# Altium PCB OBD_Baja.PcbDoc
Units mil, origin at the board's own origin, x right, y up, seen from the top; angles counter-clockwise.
Board outline 2500 x 3250 mil, 2 copper layers (Top Layer, Bottom Layer); 34 components, 27 nets, 137 pads, 53 vias.
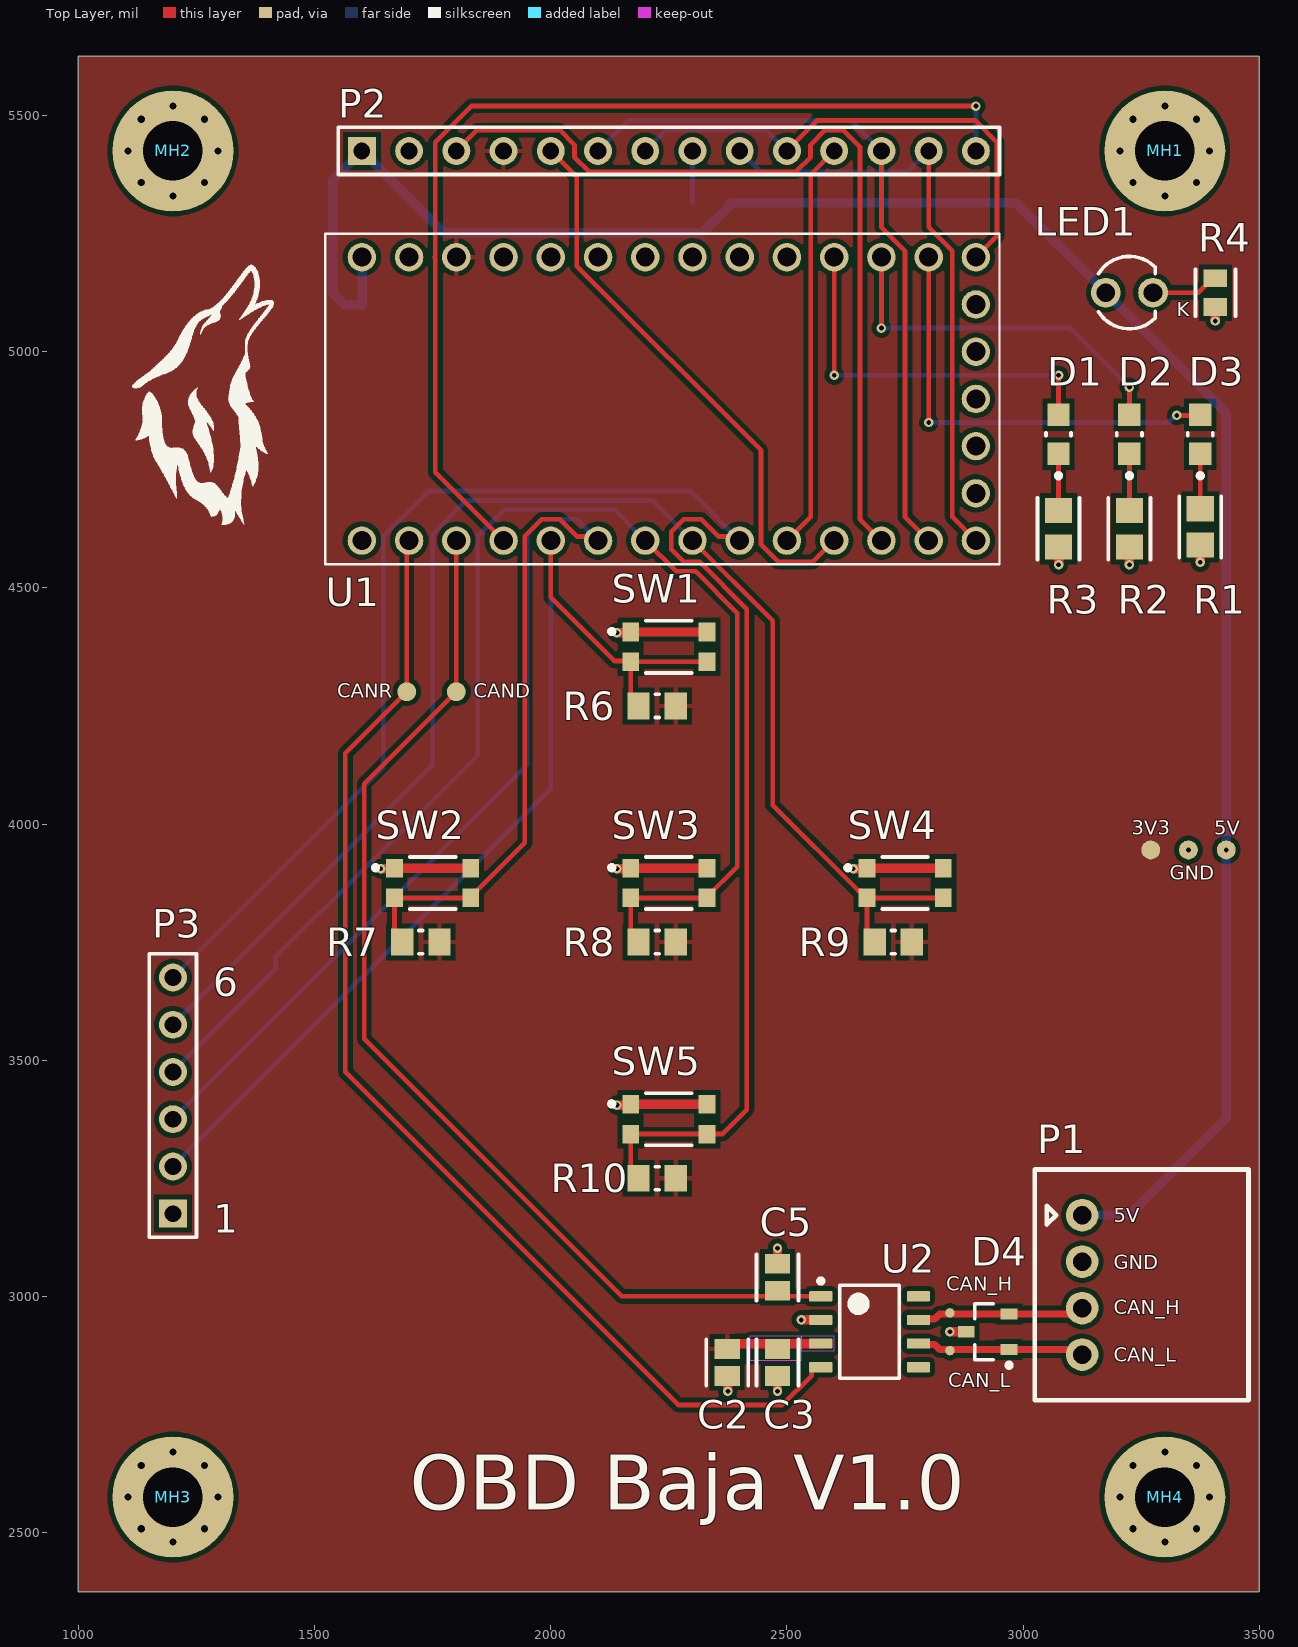
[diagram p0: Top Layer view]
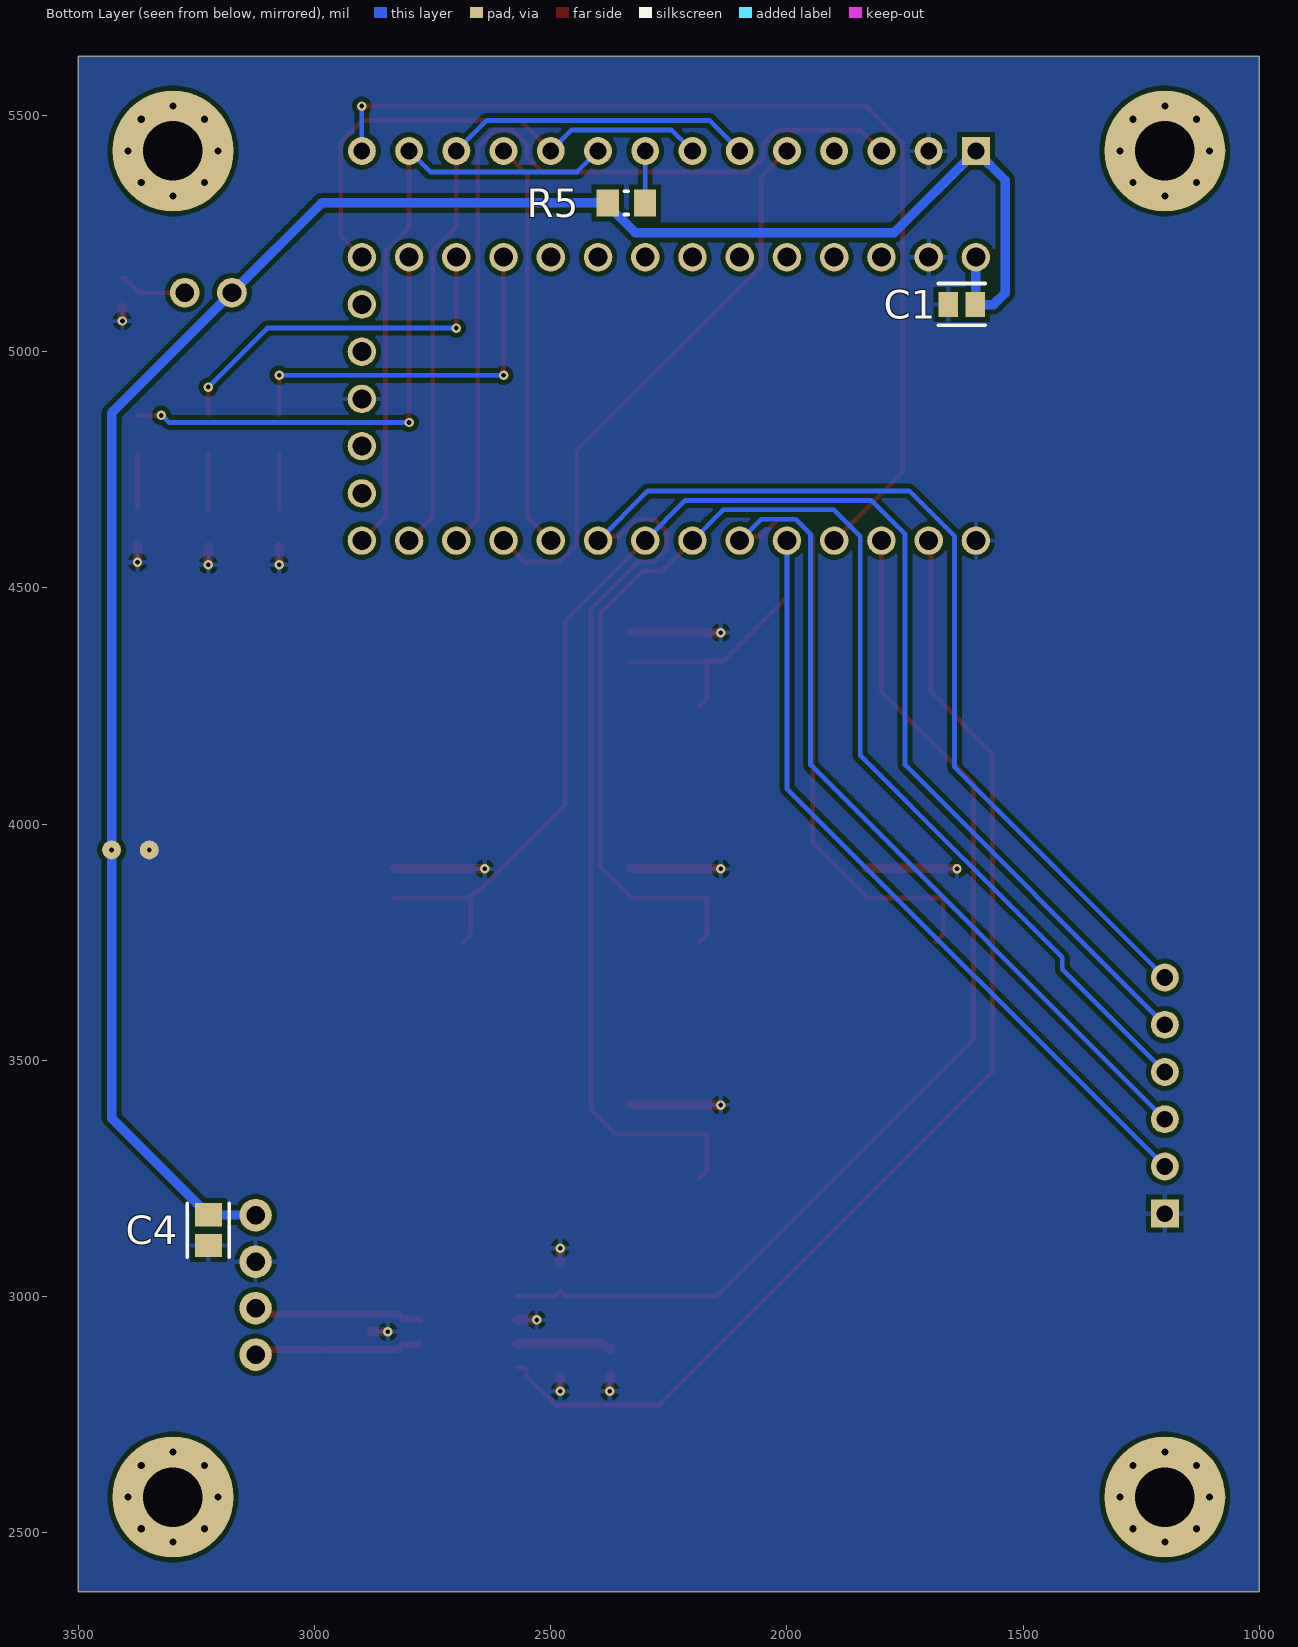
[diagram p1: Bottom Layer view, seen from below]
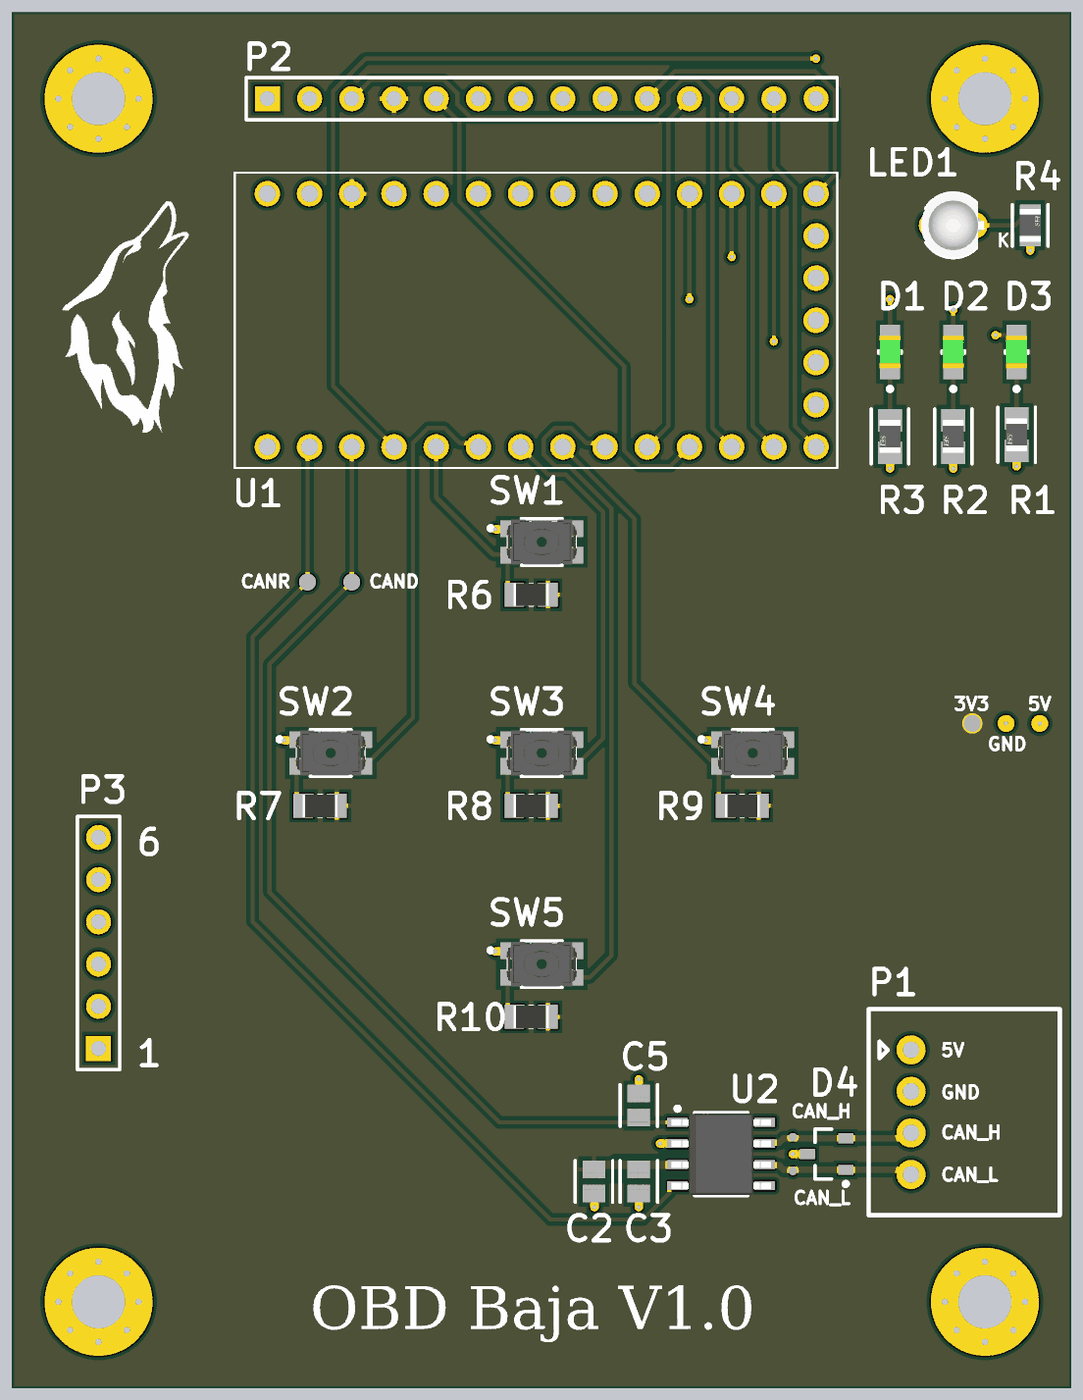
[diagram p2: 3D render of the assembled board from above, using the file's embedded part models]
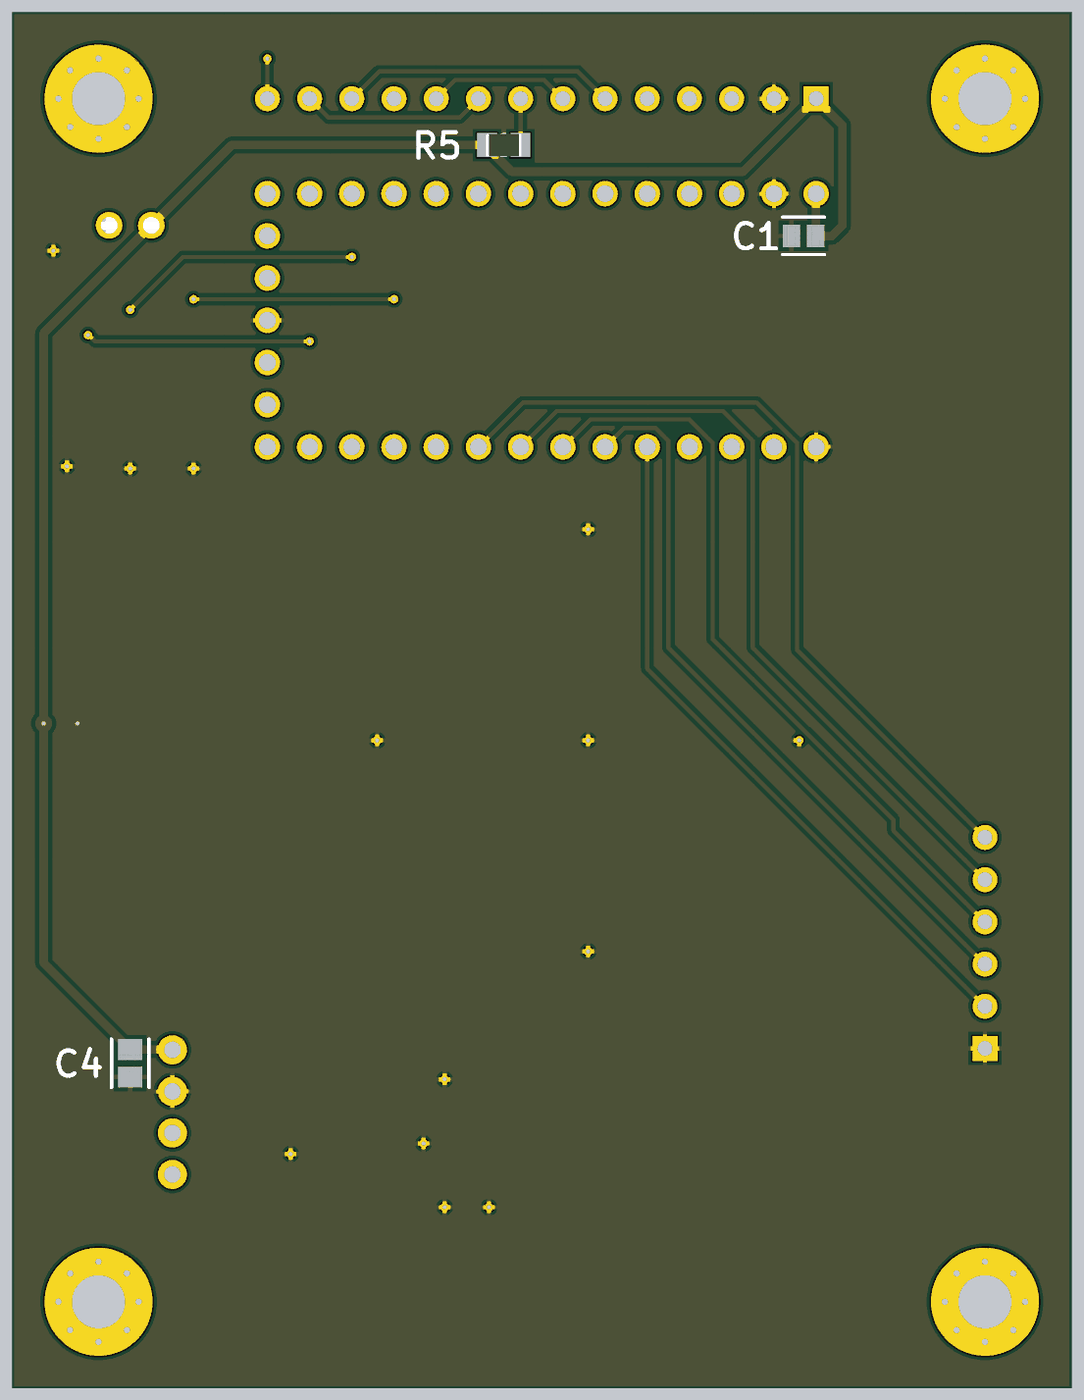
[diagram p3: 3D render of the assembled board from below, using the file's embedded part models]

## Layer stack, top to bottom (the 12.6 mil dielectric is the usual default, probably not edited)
Top Solder: solder mask 0.4, Solder Resist, Dk 3.5
Top Layer: signal copper 1.4
Dielectric 1: dielectric 12.6, FR-4, Dk 4.8
Bottom Layer: signal copper 1.4
Bottom Solder: solder mask 0.4, Solder Resist, Dk 3.5

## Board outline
1000,2375 1000,5625 3500,5625 3500,2375

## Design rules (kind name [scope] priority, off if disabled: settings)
Clearance [All] p1: gap=10 ignorepadtopadclearanceinfootprint=FALSE except(0: Arc-Hole Track-Hole SMDPad-Hole THPad-Hole Via-Hole Fill-Hole Poly-Hole Region-Hole Text-Hole)
DiffPairsRouting [All] p1: maxlimit=10 minlimit=10 mostfreqgap=10 toplayer_minwidth=15 toplayer_maxwidth=15 toplayer_prefwidth=15 bottomlayer_minwidth=15 bottomlayer_maxwidth=15 bottomlayer_prefwidth=15 maxuncoupledlength=500
HoleSize [All] p1: absolutevalues=TRUE maxlimit=200 minlimit=1 maxpercent=80.000 minpercent=20.000
NetAntennae [All] p1 off: netantennaetolerance=0
PolygonConnect [All] p1: connectstyle=Relief reliefconductorwidth=10 reliefentries=4 polygonreliefangle="90 Angle" airgapwidth=10
RoomDefinition Transceiver [InComponentClass('Transceiver')] p1 off: confinementstyle=ConfineIn formatcopy=TRUE lockcomponents=FALSE outline 0,0 2000,0 2000,1000 0,1000
RoomDefinition Screen [InComponentClass('Screen')] p2 off: confinementstyle=ConfineIn formatcopy=TRUE lockcomponents=FALSE outline 0,0 2000,0 2000,1000 0,1000
RoomDefinition LEDs [InComponentClass('LEDs')] p3 off: confinementstyle=ConfineIn formatcopy=TRUE lockcomponents=FALSE outline 0,0 2000,0 2000,1000 0,1000
RoomDefinition Buttons [InComponentClass('Buttons')] p4 off: confinementstyle=ConfineIn formatcopy=TRUE lockcomponents=FALSE outline 0,0 2000,0 2000,1000 0,1000
RoomDefinition OBD_Baja [InComponentClass('OBD_Baja')] p5: confinementstyle=ConfineIn formatcopy=TRUE lockcomponents=FALSE outline 1000,2375 3500,2375 3500,5625 1000,5625
RoutingVias [All] p1: holewidth=10 width=20 viastyle="Through Hole" minholewidth=10 minwidth=20 maxholewidth=10 maxwidth=20
SilkToSolderMaskClearance [IsPad] p1: minsilkscreentomaskgap=5 clearancetoexposedcopper=TRUE
SolderMaskExpansion [All] p1: expansion=4 istentingtop=FALSE
Width Power_Width [InNetClass('Power')] p1: maxlimit=20 minlimit=20 preferedwidth=20 minimp=50.000000 maximp=50.000000 favimp=50.000000
Width [All] p2: maxlimit=10 minlimit=10 preferedwidth=10
26 further rules are at their usual default settings.

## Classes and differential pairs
component class Transceiver: C2 C3 C4 C5 D4 P1 U2
component class OBD_Baja: C1 MH1 MH2 MH3 MH4 U1
component class Screen: P2 R5
component class LEDs: D1 D2 D3 LED1 R1 R2 R3 R4
net class Power: 3V3 +5 GND
component class Buttons: P3 R6 R7 R8 R9 R10 SW1 SW2 SW3 SW4 SW5
differential pair CAN: +CAN_H -CAN_L

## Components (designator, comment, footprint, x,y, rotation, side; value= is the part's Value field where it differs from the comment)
C1 "CL21B104KACNNNC" FP-CL21-IPC_C 1630,5100 r0 bottom
C2 "CL21B104KACNNNC" FP-CL21-IPC_C 2373.53,2860 r90 top
C3 "CL21B104KACNNNC" FP-CL21-IPC_C 2480,2860 r90 top
C4 "CL21A106KOQNNNE" FP-CL21-IPC_B 3225,3140 r270 bottom
C5 "CL21B103KAANNNC" FP-CL21-IPC_C 2480,3040 r90 top
D1 "LTST-C170GKT" FP-LTST-C170GKT-MFG 3075,4825 r90 top
D2 "LTST-C170GKT" FP-LTST-C170GKT-MFG 3225,4825 r90 top
D3 "LTST-C170GKT" FP-LTST-C170GKT-MFG 3375,4825 r90 top
D4 "PESD3V3L2BT,215" SOT95P230X110-3N 2925,2925 r180 top
LED1 "151031SS04000" "Type 3mm" 3225,5125 r0 top
MH1 "Mounting_Hole_M3" Mounting_Hole_M3 3300,5425 r0 top
MH2 "Mounting_Hole_M3" Mounting_Hole_M3 1200,5425 r0 top
MH3 "Mounting_Hole_M3" Mounting_Hole_M3 1200,2575 r0 top locked
MH4 "Mounting_Hole_M3" Mounting_Hole_M3 3300,2575 r0 top
P1 "0534" 0534260410 3125,3171.85 r270 top locked
P2 "Header 14" HDR1X14 1600,5425 r0 top locked
P3 "Header 6" HDR1X6 1200,3175 r90 top
R1 "RMCF0805JT240R" FP-RMCF0805-IPC_A 3375,4628.84 r270 top
R2 "RMCF0805JT240R" FP-RMCF0805-IPC_A 3225,4625 r270 top
R3 "RMCF0805JT240R" FP-RMCF0805-IPC_A 3075,4625 r270 top
R4 "RMCF0805JT680R" FP-RMCF0805-IPC_C 3407.26,5125 r90 top
R5 "RC0805FR-07100RL" RESC2013X60X35ML10T20 2340,5315 r180 bottom
R6 "RC0805JR-0710KL" RESC2013X60X35ML10T20 2225,4250 r0 top
R7 "RC0805JR-0710KL" RESC2013X60X35ML10T20 1725,3750 r0 top
R8 "RC0805JR-0710KL" RESC2013X60X35ML10T20 2225,3750 r0 top
R9 "RC0805JR-0710KL" RESC2013X60X35ML10T20 2725,3750 r0 top
R10 "RC0805JR-0710KL" RESC2013X60X35ML10T20 2225,3250 r0 top
SW1 "KMR631NG ULC LFS" FP-KMR631NG_ULC_LFS-MFG 2250,4375 r0 top
SW2 "KMR631NG ULC LFS" FP-KMR631NG_ULC_LFS-MFG 1750,3875 r0 top
SW3 "KMR631NG ULC LFS" FP-KMR631NG_ULC_LFS-MFG 2250,3875 r0 top
SW4 "KMR631NG ULC LFS" FP-KMR631NG_ULC_LFS-MFG 2750,3875 r0 top
SW5 "KMR631NG ULC LFS" FP-KMR631NG_ULC_LFS-MFG 2250,3375 r0 top
U1 "DEV-15583" MODULE_DEV-15583 2250,4900 r90 top
U2 "SN65HVD232D" D0008A_L 2675,2925 r0 top

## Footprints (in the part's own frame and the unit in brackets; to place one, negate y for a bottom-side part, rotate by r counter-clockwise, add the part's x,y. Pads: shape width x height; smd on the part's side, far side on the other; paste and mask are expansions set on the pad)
0534260410 [mm] "Molex 0534260410, Connector Header Through Hole, Right Angle 4 position 0.098\" (2.50mm)"
  round 1.75 hole 1: 1(0,0) 2(2.5,0) 3(5,0) 4(7.5,0)
  silkscreen extent -2.45,-2.55 9.95,8.95
D0008A_L [mm] "SOIC, 8-Leads, Body 5x4mm, Pitch 1.27mm, IPC High Density"
  rrect18% 1.25x0.55 smd: 1(-2.625,1.905) 2(-2.625,0.635) 3(-2.625,-0.635) 4(-2.625,-1.905) 5(2.625,-1.905) 6(2.625,-0.635) 7(2.625,0.635) 8(2.625,1.905)
  silkscreen extent -2.75,-2.5 1.6,2.85, body extent -3,-2.45 3,2.45, height 1.63
FP-CL21-IPC_B [mil]
  rect 49.4x57.33 smd paste+0 mask+0: 1(-32.51,0) 2(32.51,0)
  silkscreen extent -57,-44 57,44, body extent -39,-25 39,25, height 57
FP-CL21-IPC_C [mil]
  rect 41.52x53.39 smd paste+0 mask+0: 1(-28.57,0) 2(28.57,0)
  silkscreen extent -49,-44 49,44, body extent -39,-25 39,25, height 57
FP-KMR631NG_ULC_LFS-MFG [mm]
  rect 0.9x1 smd paste+0 mask+0: 1(-2.05,0.8) 2(2.05,0.8) 3(-2.05,-0.8) 4(2.05,-0.8)
  silkscreen extent -3.2,-1.4 1.22,1.4, body extent -2.6,-1.5 2.6,1.5, height 0.25
FP-LTST-C170GKT-MFG [mm]
  rect 1.2x1.2 smd paste+0 mask+0: 1(-1.05,0) 2(1.05,0)
  silkscreen extent -2.35,-0.67 0.08,0.67, body extent -1.75,-0.77 1.75,0.77, height 0.25
FP-RMCF0805-IPC_A [mil]
  rect 53.33x57.56 smd paste+0 mask+0: 1(-38.42,0) 2(38.42,0)
  silkscreen extent -65,-45 65,45, body extent -85,-48 85,48, height 10
FP-RMCF0805-IPC_C [mil]
  rect 37.58x49.69 smd paste+0 mask+0: 1(-30.54,0) 2(30.54,0)
  silkscreen extent -49,-42 49,42, body extent -53,-31 53,31, height 10
HDR1X6 [mm] "Connector; Header; 6 Position"
  rect 1.5x1.5 hole 0.9: 1(0,0)
  round 1.5 hole 0.9: 2(2.54,0) 3(5.08,0) 4(7.62,0) 5(10.16,0) 6(12.7,0)
  silkscreen extent -1.27,-1.27 13.97,1.27
HDR1X14 [mm] "Connector; Header; 14 Position"
  rect 1.5x1.5 hole 0.9: 1(0,0)
  round 1.5 hole 0.9: 2(2.54,0) 3(5.08,0) 4(7.62,0) 5(10.16,0) 6(12.7,0) 7(15.24,0) 8(17.78,0) 9(20.32,0) 10(22.86,0) 11(25.4,0) 12(27.94,0) 13(30.48,0) 14(33.02,0)
  silkscreen extent -1.27,-1.27 34.29,1.27
MODULE_DEV-15583 [mm]
  round 1.53 hole 1.02: 0(-7.62,13.97) 1(-7.62,11.43) 2(-7.62,8.89) 3(-7.62,6.35) 3.3V_1(-2.54,-16.51) 3.3V_2(7.62,11.43) 4(-7.62,3.81) 5(-7.62,1.27) 6(-7.62,-1.27) 7(-7.62,-3.81) 8(-7.62,-6.35) 9(-7.62,-8.89) 10(-7.62,-11.43) 11(-7.62,-13.97) 12(-7.62,-16.51) 13(7.62,-16.51) 14(7.62,-13.97) 15(7.62,-11.43) 16(7.62,-8.89) 17(7.62,-6.35) 18(7.62,-3.81) 19(7.62,-1.27) 20(7.62,1.27) 21(7.62,3.81) 22(7.62,6.35) 23(7.62,8.89) G1(-7.62,16.51) G2(0,-16.51) G3(7.62,13.97) ON-OFF(5.08,-16.51) PGM(2.54,-16.51) VBAT(-5.08,-16.51) VIN(7.62,16.51)
  silkscreen extent -8.89,-17.78 8.89,18.48
Mounting_Hole_M3 [mm] "Generic M3 Mounting Hole"
  round 6.5 hole 3.2: 1(0,0)
RESC2013X60X35ML10T20 [mm] "Chip Resistor, 2-Leads, Body 2.1x1.35mm, IPC Low Density"
  rect 1.2x1.45 smd: 1(-1,0) 2(1,0)
  silkscreen extent -0.1,-0.63 0.1,0.63, body extent -1.05,-0.68 1.05,0.67, height 0.6
SOT95P230X110-3N [mm] "SOT23, 3-Leads, Body 2.90x2.30mm, Pitch 0.95mm, IPC Medium Density"
  rect 0.9x0.6 smd: 1(-1.15,0.95) 2(-1.15,-0.95) 3(1.15,0)
  silkscreen extent -1.28,-1.5 0.7,1.92, body extent -0.7,-1.5 0.7,1.5, height 1.1
"Type 3mm" [mm] "THT, LED-3mm, 2pin- Body 4.15mm(max)"
  round 1.6 hole 1: 1(1.27,0) 2(-1.27,0)
  silkscreen extent -1.66,-1.95 1.4,1.95, body extent -1.93,-1.94 1.87,1.94, height 10.5

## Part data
C1 C2 C3: library part CMP-13271-002854-1, "CL21 Series 0805 100nF 25V ±10% Tolerance X7R Multilayer Ceramic Chip Capacitor", Capacitance=100nF, Case Code (Imperial)=0805, Case Code (Metric)=2012, Dielectric=X7R, Max Operating Temperature=125°C, Min Operating Temperature=-55°C, Package Quantity=1, Tolerance=10%, Voltage=25V
C4: library part CMP-2000-06102-2, "CL21 Series 0805 10uF 16V ±10% Tolerance X5R Multilayer Ceramic Chip Capacitor", Capacitance=10uF, Case Code (Imperial)=0805, Case Code (Metric)=2012, Dielectric=X7R, Max Operating Temperature=85°C, Min Operating Temperature=-55°C, Package Quantity=1, Tolerance=10%, Voltage=16V
C5: library part CMP-13271-004188-1, "CL21 Series 0805 10nF 25V ±10% Tolerance X7R Multilayer Ceramic Chip Capacitor", Capacitance=10nF, Case Code (Imperial)=0805, Case Code (Metric)=2012, Dielectric=X7R, Max Operating Temperature=125°C, Min Operating Temperature=-55°C, Package Quantity=1, Tolerance=20%, Voltage Rating=50V
D1 D2 D3: library part CMP-1674-00002-6, "LED GREEN CLEAR SMD", Case Code (Imperial)=0805, Case Code (Metric)=2012, Color=Green, Forward Current=30mA, Forward Voltage=2.1V, Lens Color=Colorless, Max Operating Temperature=85°C, Min Operating Temperature=-55°C, Package Quantity=1, Power Dissipation=100mW, Reverse Voltage=5V, Test Current=10mA
D4: library part CMP-00002-6, "PESD3V3L2BT - Low capacitance double bidirectional ESD protection diode in SOT23"
LED1: library part CMP-1488-00005-1, "THT LED round mono-color color lens, WL-TMRW, Super Red", Emitting color="Super Red", Manufacturer="Wuerth Elektronik"
MH1 MH2 MH3 MH4: library part CMP-00001-4, "Generic M3 Mounting Hole"
P1: library part CMP-00000-3, "2.50mm Pitch Mini-Lock Wire-to-Board Header Right Angle Friction and Positive Lock 4 Circuits", Color=White, Contact Resistance=20mR, Max Operating Temperature=105°C, Min Operating Temperature=-40°C
P2: "Header, 14-Pin"
P3: "Header, 6-Pin"
R1 R2 R3: library part CMP-26527-005851-1, "240Ω ±5% 0.125W 0805 Thick Film Chip Resistor AEC-Q200 compliant", Case Code (Imperial)=0805, Case Code (Metric)=2012, Max Operating Temperature=155°C, Max Power Dissipation=125mW, Min Operating Temperature=-55°C, Resistance=240R, Resistor Type="Thick Film", Temperature Coefficient=200ppm/°C, Tolerance=5%
R4: library part CMP-26527-000032-1, "680Ω ±5% 0.125W 0805 Thick Film Chip Resistor AEC-Q200 compliant", Case Code (Imperial)=0805, Case Code (Metric)=2012, Max Operating Temperature=155°C, Max Power Dissipation=125mW, Min Operating Temperature=-55°C, Resistance=680R, Resistor Type="Thick Film", Temperature Coefficient=200ppm/°C, Tolerance=5%
R5: library part CMP-2100-03669-1, "Chip Resistor, 100 Ohm, +/-1%, 0.125 W, -55 to 155 degC, 0805 (2012 Metric), RoHS, Tape and Reel", Case Code (Imperial)=0805, Case Code (Metric)=2012, Manufacturer=Yageo, Max Operating Temperature=155degC, Max Power Dissipation=125mW, Min Operating Temperature=-55degC, Package Description="2-Pin Surface Mounted Device, Body 2 x 1.25 mm", Package Quantity=1, Resistance=100Ohm, Temperature Coefficient=100ppm/degreesC, Tolerance=1%, Voltage Rating=150V
R6 R7 R8 R9 R10: library part CMP-2000-05025-1, "Chip Resistor, 10 KOhm, +/- 5%, 0.125 W, -55 to 155 degC, 0805 (2012 Metric), RoHS, Tape and Reel", Manufacturer=Yageo, Package Description="2-Pin Surface Mounted Device, Body 2 x 1.25 mm", Package Reference=805, Power Rating=250mW, Resistance=10kohm, Resistance Tolerance=±5%, Resistor Case Style=0805[2012Metric], Resistor Element Type=ThickFilm, Temperature Coefficient=±100ppm/degC, Voltage Rating=150V
SW1 SW2 SW3 SW4 SW5: library part CMP-10040-000019-1, "SWITCH TACTILE SPST-NO 50MA 32V", Max Operating Temperature=85°C, Min Operating Temperature=-40°C, Operating Force=300gf, Ratings=IP67
U1: library part CMP-301-000000-1, "RT1062 Teensy 4.0 i.MX ARMÂ® CortexÂ®-M7 MPU Embedded Evaluation Board", Package=None
U2: library part CMP-0315-00073-2, "3.3 V CAN Transceiver, 17 mA, -40 to 85 degC, 8-pin SOIC (D), Green (RoHS & no Sb/Br)", Drivers Per Package=1, Manufacturer="Texas Instruments", Rating=Catalog, Supply Voltage(s)(V)=3.3

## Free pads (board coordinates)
  round 40 hole 10 mask+4: 8(3430,3945) TP(3350,3945)
  round 40 smd: TP(1695,4280) TP(1800,4280) TP(3270,3945)
  round 20 smd: TP(2845,2885) TP(2845,2965)

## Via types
v1: diameter 25, hole 15, Top Layer to Bottom Layer, 32 vias
v2: diameter 20, hole 10, Top Layer to Bottom Layer, 21 vias

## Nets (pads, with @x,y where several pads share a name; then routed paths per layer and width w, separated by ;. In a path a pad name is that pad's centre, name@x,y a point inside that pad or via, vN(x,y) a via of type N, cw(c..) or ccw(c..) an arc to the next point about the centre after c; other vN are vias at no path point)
3V3: C2.2 C3.2 P2.4 pad.TP@3270,3945 R6.2 R7.2 R8.2 R9.2 R10.2 U1.3.3V_2 U2.3 | length 202.9
  Top Layer w20: C2.2 2379.47,2888.57 2390.89,2900 U2.3
+5: C1.1 C4.1 LED1.2 P1.1 P2.1 pad.8 R5.1 U1.VIN | length 4498.2
  Bottom Layer w20: U1.VIN 1600.71,5199.29 1600.71,5099.95 1601.04,5099.62 1562.38,5099.62 1538,5124 1538,5363 P2.1 1772.92,5252.08 2321.37,5252.08 2379.37,5310.08 R5.1 2985,5315 LED1.2 3430,4870 3430,3377.51 C4.1 3224.67,3172.18 3125.33,3172.18 P1.1
B_C: P3.4 R8.1 SW3.3 SW3.4 U1.5 | length 2956.4
  Top Layer w10: R8.1 2169.29,3766.34 SW3.3 SW3.4 2330.71,3845.47 2395,3909.76 2395,4446.6 2306.72,4534.88 2265.12,4534.88 U1.5
  Bottom Layer w10: P3.4 1417.02,3692.02 1417.02,3717.37 1624.82,3925.18 1625.18,3925.18 1845.12,4145.12 1845.12,4608.92 1901.31,4665.12 2134.88,4665.12 U1.5
B_DN: P3.6 R10.1 SW5.3 SW5.4 U1.7 | length 3808.3
  Top Layer w10: R10.1 2169.29,3266.34 SW5.3 SW5.4 2363.42,3343.5 2415,3395.08 2415,4454.88 2315,4554.88 2281.31,4554.88 2254.88,4581.31 2254.88,4618.69 2281.31,4645.12 2318.69,4645.12 2354.88,4608.92 2391.08,4608.92 U1.7
  Bottom Layer w10: P3.6 1645.12,4120.12 1645.12,4608.92 1741.31,4705.12 2294.88,4705.12 U1.7
B_L: P3.3 R7.1 SW2.3 SW2.4 U1.4 | length 2994.2
  Top Layer w10: R7.1 1669.29,3766.34 SW2.3 SW2.4 1830.71,3845.47 1945.12,3959.88 1945.12,4608.92 1981.31,4645.12 2018.69,4645.12 2054.88,4608.92 2091.08,4608.92 U1.4
  Bottom Layer w10: P3.3 1950,4125 1950,4613.81 1981.31,4645.12 2054.88,4645.12 U1.4
B_R: P3.5 R9.1 SW4.3 SW4.4 U1.6 | length 3055.6
  Top Layer w10: U1.6 2469.63,4430.37 2469.63,4040.02 2651.46,3858.19 2656.58,3858.19 2669.29,3845.47 SW4.3 ; R9.1 2669.29,3766.34 SW4.3 ; SW4.4 SW4.3
  Bottom Layer w10: P3.5 1750,4125 1750,4613.81 1821.31,4685.12 2214.88,4685.12 U1.6
B_UP: P3.2 R6.1 SW1.3 SW1.4 U1.3 | length 2263.9
  Top Layer w10: U1.3 2000,4480 2135,4345 2167.8,4345 SW1.3 ; R6.1 2169.29,4266.34 SW1.3 ; SW1.4 SW1.3
  Bottom Layer w10: P3.2 2000,4075 U1.3
CAN_H: D4.2 P1.3 pad.TP@2845,2965 U2.7 | length 351.1
  Top Layer w15: U2.7 2780.02,2951.67 2812.78,2951.67 2823.51,2962.4 D4.2 ; D4.2@2976.18,2962.4 3097.82,2962.4 3110.42,2975 P1.3
CAN_L: D4.1 P1.4 pad.TP@2845,2885 U2.6 | length 350.5
  Top Layer w15: U2.6 2780.02,2898.33 2812.78,2898.33 2823.51,2887.6 D4.1 ; D4.1@2976.18,2887.6 3099.39,2887.6 3110.42,2876.58 P1.4
CAND: C5.1 pad.TP@1800,4280 U1.1 U2.1 | length 2337.6
  Top Layer w10: U1.1 1800,4280 1605,4085 1605,3545 2150,3000 2468.57,3000 C5.1 2491.43,3000 U2.1
CANR: pad.TP@1695,4280 U1.0 U2.4 | length 2519.8
  Top Layer w10: U1.0 1695,4595 1695,4280 1565,4150 1565,3475 2270,2770 2490,2770 2552.05,2832.05 2552.05,2844.17 2557.87,2850 U2.4
CS: P2.3 U1.10 | length 1844.4
  Top Layer w10: P2.3 1844.53,5469.53 2018.44,5469.53 2050,5437.97 2050,5412.03 2081.56,5380.47 2518.44,5380.47 2550,5412.03 2550,5437.97 2581.56,5469.53 2618.44,5469.53 2654.42,5433.56 2654.42,4645.58 U1.10
D/C: P2.5 U1.9 | length 1206.9
  Top Layer w10: P2.5 2054.88,5370.12 2054.88,5181.31 2445.12,4791.08 2445.12,4591.08 2481.31,4554.88 2554.88,4554.88 U1.9
DEBUG1: D1.2 U1.16 | length 808.7
  Top Layer w10: v2(2600,4950) U1.16 ; D1.2 v2(3075,4950)
  Bottom Layer w10: v2(2600,4950) v2(3075,4950)
DEBUG2: D2.2 U1.15 | length 785.4
  Top Layer w10: v2(2700,5050) U1.15 ; D2.2 v2(3225,4925)
  Bottom Layer w10: v2(2700,5050) 3100,5050 v2(3225,4925)
DEBUG3: D3.2 U1.14 | length 931.8
  Top Layer w10: v2(2800,4850) U1.14 ; v2(3325,4865) 3373.66,4865 D3.2
  Bottom Layer w10: v2(2800,4850) 3307.29,4850 3322.29,4865 v2(3325,4865)
GND: C1.2 C2.1 C3.1 C4.2 C5.2 D4.3 P1.2 P2.2 P3.1 pad.TP@3350,3945 R1.2 R2.2 R3.2 R4.1 SW1.1 SW1.2 SW2.1 SW2.2 SW3.1 SW3.2 SW4.1 SW4.2 SW5.1 SW5.2 U1.G1 U1.G2 U1.G3 U2.2 | length 1273.1
  Top Layer w20: v2(1640,3905) 1667.8,3905 SW2.1 SW2.2 ; v2(2140,3405) 2167.8,3405 SW5.1 SW5.2 ; v2(2140,3905) 2167.8,3905 SW3.1 SW3.2 ; v2(2140,4405) 2166.58,4405 2168.07,4406.5 SW1.2 ; C2.1 2375,2829.96 v2(2375,2799) ; v2(2480,2799) C3.1 ; C5.2 v2(2480,3102) ; v2(2530,2950) U2.2 ; v2(2640,3905) 2667.8,3905 SW4.1 SW4.2 ; v2(2845,2925) D4.3 ; v2(3075,4549) R3.2 ; v2(3225,4549) R2.2 ; v2(3375,4554) R1.2 ; v2(3407,5065) 3407,5094.19 R4.1
NetD1_1: D1.1 R3.1 | length 120.2
  Top Layer w10: R3.1 D1.1
NetD2_1: D2.1 R2.1 | length 120.2
  Top Layer w10: R2.1 D2.1
NetD3_1: D3.1 R1.1 | length 116.4
  Top Layer w10: R1.1 D3.1
NetLED1_1: LED1.1 R4.2 | length 144.9
  Top Layer w10: LED1.1 3370.67,5125 3401.21,5155.54 R4.2
NetP2_8: P2.8 R5.2 | length 110.3
  Bottom Layer w10: P2.8 2300,5315.63 R5.2
SCK: P2.7 P2.10 U1.13 | length 1089.1
  Top Layer w10: P2.10 2564.53,5489.53 2898.44,5489.53 2944.53,5443.44 2944.53,5244.53 U1.13
  Bottom Layer w10: P2.7 2244.53,5469.53 2455.47,5469.53 P2.10
SDI: P2.6 P2.12 U1.11 | length 1519.9
  Top Layer w10: P2.12 2700,5263.81 2749.89,5213.92 2749.89,4650.11 U1.11
  Bottom Layer w10: P2.6 2164.53,5489.53 2635.47,5489.53 P2.12
SDO: P2.9 P2.13 U1.12 | length 1303.3
  Top Layer w10: P2.13 2800,5263.81 2849.89,5213.92 2849.89,4650.11 U1.12
  Bottom Layer w10: P2.9 2444.53,5380.47 2755.47,5380.47 P2.13
T_CS: P2.11 U1.8 | length 866.4
  Top Layer w10: U1.8 2550.11,4650.11 2550.11,5375.11 P2.11
T_IRQ: P2.14 U1.2 | length 2174.6
  Top Layer w10: U1.2 1758.4,4741.6 1755.47,4744.53 1755.47,5192.72 cw(c1800,5200) 1755.47,5207.28 1755.47,5443.44 1832.03,5520 v2(2900,5520)
  Bottom Layer w10: P2.14 v2(2900,5520)
pads on no net: MH1.1 MH2.1 MH3.1 MH4.1 U1.3.3V_1 U1.17 U1.18 U1.19 U1.20 U1.21 U1.22 U1.23 U1.ON-OFF U1.PGM U1.VBAT U2.5 U2.8
copper on no net:
  other v1: 1200,2480 3300,2480 1132.82,2507.82 1267.18,2507.82 3232.82,2507.82 3367.18,2507.82 1105,2575 1295,2575 3205,2575 3395,2575 1132.82,2642.18 1267.18,2642.18 3232.82,2642.18 3367.18,2642.18 1200,2670 3300,2670 1200,5330 3300,5330 1132.82,5357.82 1267.18,5357.82 3232.82,5357.82 3367.18,5357.82 1105,5425 1295,5425 3205,5425 3395,5425 1132.82,5492.18 1267.18,5492.18 3232.82,5492.18 3367.18,5492.18 1200,5520 3300,5520

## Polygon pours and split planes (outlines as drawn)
3V3 on Top Layer "3V3_L01_P000" (solid, pour order 0): 1000,5625 1000,2375 3500,2375 3500,5625
GND on Bottom Layer "GND_L02_P001" (solid, pour order 1): 1000,5625 1000,2375 3500,2375 3500,5625

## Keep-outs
Top Layer:
  rectangle: 2530,2885 2600,2915
  rectangle: 2421,2865 2530,2915

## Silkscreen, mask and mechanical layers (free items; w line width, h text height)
Top Overlay:
  drawing of 5 lines, arcs and shapes, not listed
  text "CANR" at 1548.04,4267 h30
  text "CAND" at 1837,4267 h30
  text "3V3" at 3230.01,3977 h30
  text "5V" at 3405.01,3977 h30
  text "GND" at 3310.01,3882 h30
  text "6" at 1285,3635 h60
  text "5V" at 3192,3157 h30
  text "1" at 1285,3135 h60
  text "GND" at 3192,3057 h30
  text "CAN_H" at 2837,3012 h30
  text "CAN_H" at 3192,2962 h30
  text "CAN_L" at 3192,2862 h30
  text "CAN_L" at 2842,2807 h30
  text "OBD Baja V1.0" at 1701.14,2510.32 h200
Board Shape:
  the board outline again, w10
